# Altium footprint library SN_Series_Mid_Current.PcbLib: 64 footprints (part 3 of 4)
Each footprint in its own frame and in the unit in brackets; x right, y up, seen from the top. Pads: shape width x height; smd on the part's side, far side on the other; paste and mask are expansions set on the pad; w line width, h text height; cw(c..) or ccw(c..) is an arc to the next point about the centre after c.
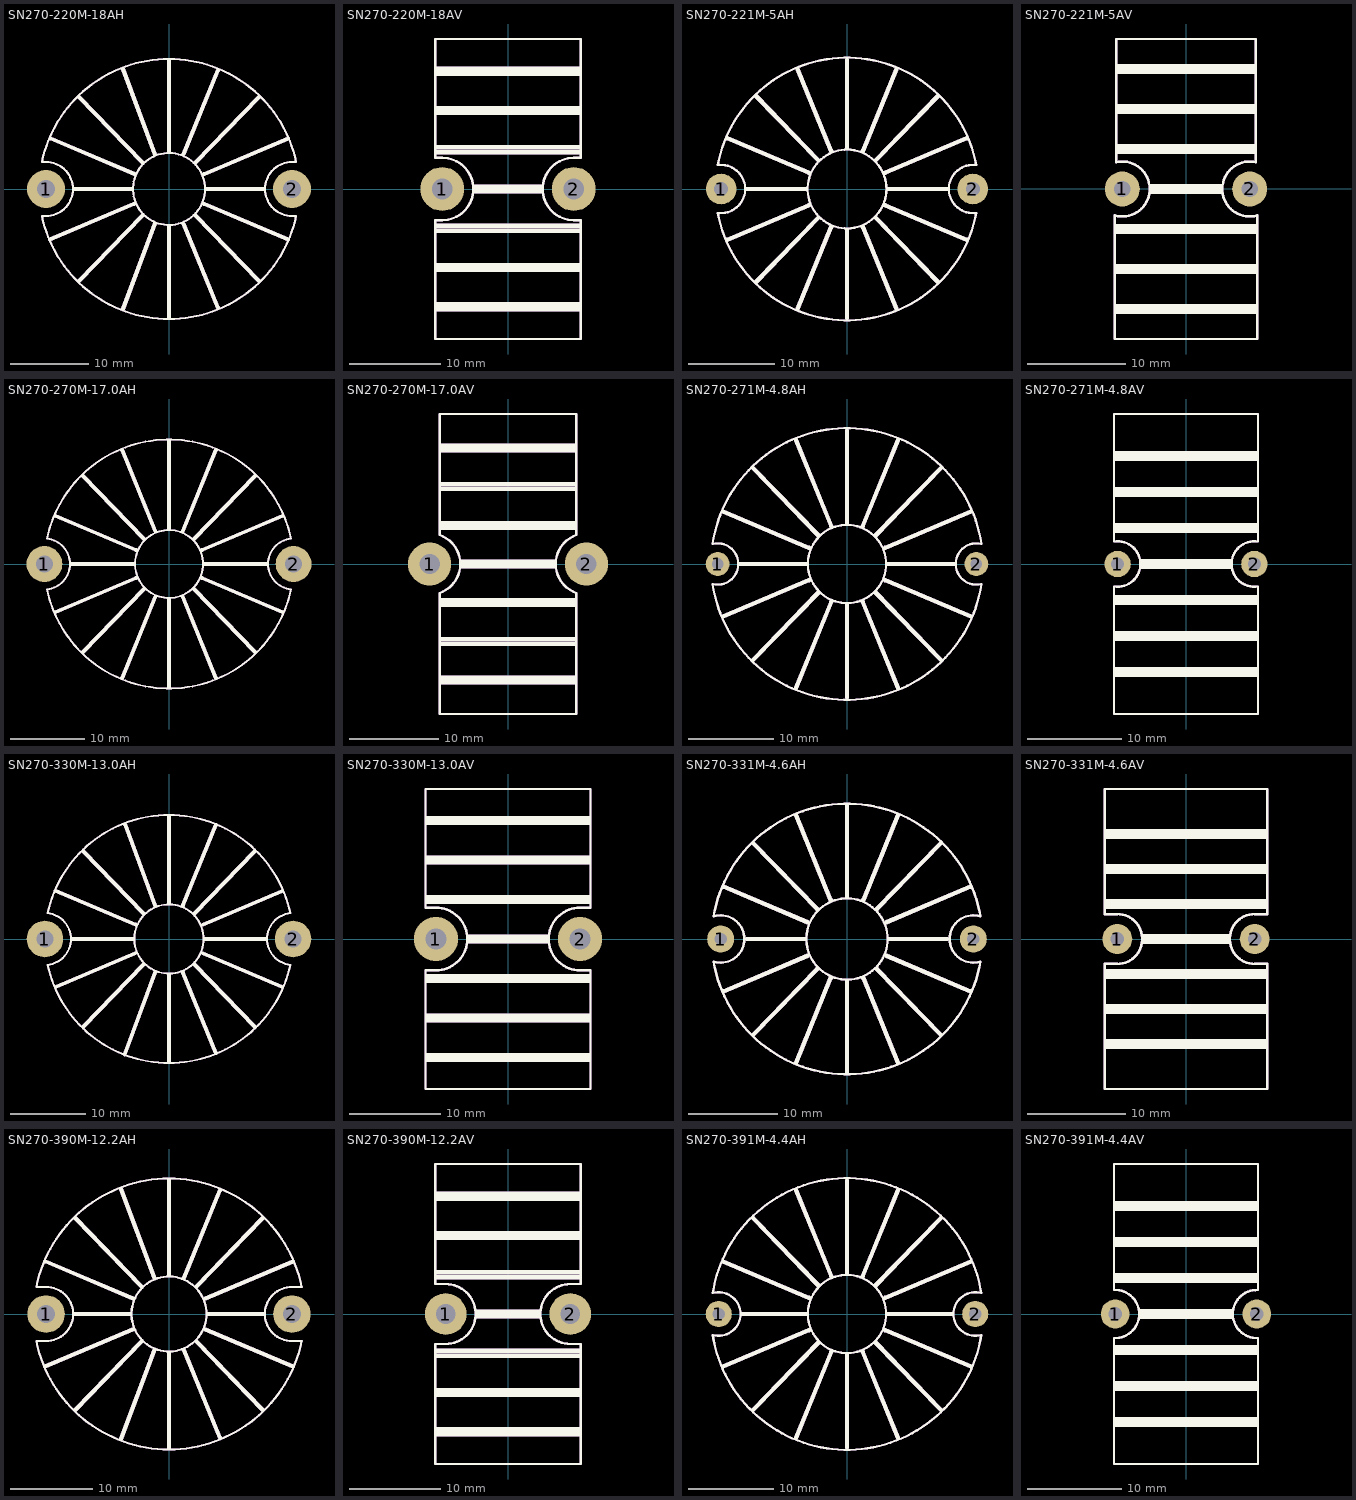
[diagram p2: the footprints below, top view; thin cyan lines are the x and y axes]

## SN270-220M-18AH [mil]
pads (2):
  round 190 hole 90: 1(-615,0) 2(615,0)
Top Overlay:
  circle w10: c0,0 r180
  lines w10: -635.83,-135 ccw(c0,0) 635.83,-135 615,-135 cw(c615,0) 615,135 635.83,135 ccw(c0,0) -635.83,135 -615,135 cw(c-615,0) -615,-135 -635.83,-135
  lines w19.68: -596.03,-252.56 -175.3,-74.28 ; -593.79,252.95 -173.05,74.68 ; -475,0 -185,0 ; -450,-460 -132.7,-132.43 ; -450,460 -132.7,132.43 ; -230,-600 -70.44,-171.87 ; -230,600 -70.44,171.87 ; 0,-640 0,-185 ; 0,185 0,640 ; 72.46,-173.99 243.97,-592.47 ; 72.46,173.99 243.97,592.47 ; 132.5,-132.5 450,-460 ; 132.5,132.5 450,460 ; 175.3,-74.28 596.03,-252.56 ; 175.3,74.28 596.03,252.56 ; 185,0 475,0
Mechanical 29:
  circle w10: c0,0 r180
  lines w10: -635.83,-135 ccw(c0,0) 635.83,-135 615,-135 cw(c615,0) 615,135 635.83,135 ccw(c0,0) -635.83,135 -615,135 cw(c-615,0) -615,-135 -635.83,-135
  lines w19.68: -596.03,-252.56 -175.3,-74.28 ; -593.79,252.95 -173.05,74.68 ; -475,0 -185,0 ; -450,-460 -132.7,-132.43 ; -450,460 -132.7,132.43 ; -230,-600 -70.44,-171.87 ; -230,600 -70.44,171.87 ; 0,-640 0,-185 ; 0,185 0,640 ; 72.46,-173.99 243.97,-592.47 ; 72.46,173.99 243.97,592.47 ; 132.5,-132.5 450,-460 ; 132.5,132.5 450,460 ; 175.3,-74.28 596.03,-252.56 ; 175.3,74.28 596.03,252.56 ; 185,0 475,0
  text "'.Designator'" at -290,145.15 h400

## SN270-220M-18AV [mil]
pads (2):
  round 190 hole 90: 1(-285,0) 2(285,0)
Top Overlay:
  lines w10: -315,-650 315,-650 315,-135 285,-135 cw(c285,0) 285,135 315,135 315,650 -315,650 -315,135 -285,135 cw(c-285,0) -285,-135 -315,-135 -315,-650
  lines w19.68: -310,-520 310,-520 ; -310,-500 310,-500 ; -310,-350 310,-350 ; -310,-330 310,-330 ; -310,-180 310,-180 ; -310,-160 310,-160 ; -310,160 310,160 ; -310,180 310,180 ; -310,330 310,330 ; -310,350 310,350 ; -310,500 310,500 ; -310,520 310,520 ; -145,-10 145,-10 ; -145,10 145,10
Mechanical 29:
  lines w10: -315,-650 315,-650 315,-135 285,-135 cw(c285,0) 285,135 315,135 315,650 -315,650 -315,135 -285,135 cw(c-285,0) -285,-135 -315,-135 -315,-650
  lines w19.68: -310,-520 310,-520 ; -310,-500 310,-500 ; -310,-350 310,-350 ; -310,-330 310,-330 ; -310,-180 310,-180 ; -310,-160 310,-160 ; -310,160 310,160 ; -310,180 310,180 ; -310,330 310,330 ; -310,350 310,350 ; -310,500 310,500 ; -310,520 310,520 ; -145,-10 145,-10 ; -145,10 145,10
  text "'.Designator'" at -1750,-64.85 h400

## SN270-221M-5AH [mil]
pads (2):
  round 140 hole 65: 1(-575,0) 2(575,0)
Top Overlay:
  circle w10: c0,0 r180
  lines w10: -589.93,-109.45 ccw(c0,0) 589.93,-109.45 ; -589.93,109.45 cw(c0,0) 589.93,109.45 ; -589.87,-108.99 ccw(c-575,0) -589.87,108.99 ; 589.87,-108.99 cw(c575,0) 589.87,108.99
  lines w19.68: -548.21,-232.29 -175.3,-74.28 ; -548.21,232.29 -175.3,74.28 ; -460,0 -185,0 ; -414.4,-423.28 -132.5,-132.5 ; -414.4,423.28 -132.5,132.5 ; -226.04,-548.74 -72.46,-173.99 ; -226.04,548.74 -72.46,173.99 ; 0,-590 0,-185 ; 0,185 0,590 ; 72.46,-173.99 226.04,-548.74 ; 72.46,173.99 226.04,548.74 ; 132.5,-132.5 414.4,-423.28 ; 132.5,132.5 414.4,423.28 ; 175.3,-74.28 548.21,-232.29 ; 175.3,74.28 548.21,232.29 ; 185,0 460,0
Mechanical 29:
  circle w10: c0,0 r180
  lines w10: -589.93,-109.45 ccw(c0,0) 589.93,-109.45 ; -589.93,109.45 cw(c0,0) 589.93,109.45 ; -589.87,-108.99 ccw(c-575,0) -589.87,108.99 ; 589.87,-108.99 cw(c575,0) 589.87,108.99
  lines w19.68: -548.21,-232.29 -175.3,-74.28 ; -548.21,232.29 -175.3,74.28 ; -460,0 -185,0 ; -414.4,-423.28 -132.5,-132.5 ; -414.4,423.28 -132.5,132.5 ; -226.04,-548.74 -72.46,-173.99 ; -226.04,548.74 -72.46,173.99 ; 0,-590 0,-185 ; 0,185 0,590 ; 72.46,-173.99 226.04,-548.74 ; 72.46,173.99 226.04,548.74 ; 132.5,-132.5 414.4,-423.28 ; 132.5,132.5 414.4,423.28 ; 175.3,-74.28 548.21,-232.29 ; 175.3,74.28 548.21,232.29 ; 185,0 460,0
  text "'.Designator'" at -290,145.15 h400

## SN270-221M-5AV [mil]
pads (2):
  round 140 hole 65: 1(-255,0) 2(255,0)
Top Overlay:
  lines w10: -285,-106.19 -285,-600 285,-600 285,-106.19 ; -284.91,-105.86 ccw(c-255,0) -279.95,107.13 ; -280,107.37 -280,600 280,600 280,107.37 ; 279.95,107.13 ccw(c255,0) 284.91,-105.86
  lines w19.68: -280,-170 280,-170 ; -280,-150 280,-150 ; -277,-490 278,-490 ; -277,-470 278,-470 ; -277,-330 278,-330 ; -277,-310 278,-310 ; -275,150 271,150 ; -275,170 271,170 ; -275,310 271,310 ; -275,330 271,330 ; -275,470 271,470 ; -275,490 271,490 ; -140,-10 140,-10 ; -140,10 140,10
Mechanical 29:
  lines w10: -285,-106.19 -285,-600 285,-600 285,-106.19 ; -284.91,-105.86 ccw(c-255,0) -279.95,107.13 ; -280,107.37 -280,600 280,600 280,107.37 ; 279.95,107.13 ccw(c255,0) 284.91,-105.86
  lines w19.68: -280,-170 280,-170 ; -280,-150 280,-150 ; -277,-490 278,-490 ; -277,-470 278,-470 ; -277,-330 278,-330 ; -277,-310 278,-310 ; -275,150 271,150 ; -275,170 271,170 ; -275,310 271,310 ; -275,330 271,330 ; -275,470 271,470 ; -275,490 271,490 ; -140,-10 140,-10 ; -140,10 140,10
  text "'.Designator'" at -1750,-64.85 h400

## SN270-270M-17.0AH [mil]
pads (2):
  round 190 hole 90: 1(-660,0) 2(660,0)
Top Overlay:
  circle w10: c0,0 r180
  lines w10: -646.19,-134.29 ccw(c0,0) 646.19,-134.29 cw(c660,0) 646.19,134.29 ccw(c0,0) -646.19,134.29 cw(c-660,0) -646.19,-134.29
  lines w19.68: -603.45,-255.7 -175.3,-74.28 ; -603.45,255.7 -175.3,74.28 ; -520,0 -185,0 ; -456.17,-466.36 -132.5,-132.5 ; -456.17,466.36 -132.5,132.5 ; -248.8,-604.26 -72.46,-173.99 ; -248.8,604.26 -72.46,173.99 ; 0,-650 0,-185 ; 0,185 0,650 ; 72.46,-173.99 248.8,-604.26 ; 72.46,173.99 248.8,604.26 ; 132.5,-132.5 456.17,-466.36 ; 132.5,132.5 456.17,466.36 ; 175.3,-74.28 603.45,-255.7 ; 175.3,74.28 603.45,255.7 ; 185,0 520,0
Mechanical 29:
  circle w10: c0,0 r180
  lines w10: -646.19,-134.29 ccw(c0,0) 646.19,-134.29 cw(c660,0) 646.19,134.29 ccw(c0,0) -646.19,134.29 cw(c-660,0) -646.19,-134.29
  lines w19.68: -603.45,-255.7 -175.3,-74.28 ; -603.45,255.7 -175.3,74.28 ; -520,0 -185,0 ; -456.17,-466.36 -132.5,-132.5 ; -456.17,466.36 -132.5,132.5 ; -248.8,-604.26 -72.46,-173.99 ; -248.8,604.26 -72.46,173.99 ; 0,-650 0,-185 ; 0,185 0,650 ; 72.46,-173.99 248.8,-604.26 ; 72.46,173.99 248.8,604.26 ; 132.5,-132.5 456.17,-466.36 ; 132.5,132.5 456.17,466.36 ; 175.3,-74.28 603.45,-255.7 ; 175.3,74.28 603.45,255.7 ; 185,0 520,0
  text "'.Designator'" at -290,145.15 h400

## SN270-270M-17.0AV [mil]
pads (2):
  round 190 hole 90: 1(-345,0) 2(345,0)
Top Overlay:
  lines w10: -300.09,127.31 cw(c-345,0) -300,-127.28 -300,-660 300,-660 300,-127.57 ; -300,127.57 -300,660 300,660 300,127.57 ; 300.09,-127.31 cw(c345,0) 300.09,127.31
  lines w19.68: -295,-520 295,-520 ; -295,-500 295,-500 ; -295,-350 295,-350 ; -295,-330 295,-330 ; -295,-180 295,-180 ; -295,-160 295,-160 ; -295,160 295,160 ; -295,180 295,180 ; -295,330 295,330 ; -295,350 295,350 ; -295,500 295,500 ; -295,520 295,520 ; -205,-10 205,-10 ; -205,10 205,10
Mechanical 29:
  lines w10: -300.09,127.31 cw(c-345,0) -300,-127.28 -300,-660 300,-660 300,-127.57 ; -300,127.57 -300,660 300,660 300,127.57 ; 300.09,-127.31 cw(c345,0) 300.09,127.31
  lines w19.68: -295,-520 295,-520 ; -295,-500 295,-500 ; -295,-350 295,-350 ; -295,-330 295,-330 ; -295,-180 295,-180 ; -295,-160 295,-160 ; -295,160 295,160 ; -295,180 295,180 ; -295,330 295,330 ; -295,350 295,350 ; -295,500 295,500 ; -295,520 295,520 ; -205,-10 205,-10 ; -205,10 205,10
  text "'.Designator'" at -1750,-64.85 h400

## SN270-271M-4.8AH [mil]
pads (2):
  round 110 hole 53: 1(-595,0) 2(595,0)
Top Overlay:
  circle w10: c0,0 r180
  lines w10: -618.06,-92.87 ccw(c0,0) 618.05,-92.95 ; -618.06,92.87 cw(c0,0) 618.08,92.76 ; -617.89,-92.2 ccw(c-595,0) -617.89,92.2 ; 617.87,-92.21 cw(c595,0) 617.94,92.19
  lines w19.68: -569.45,-241.29 -175.3,-74.28 ; -569.45,241.29 -175.3,74.28 ; -495,0 -185,0 ; -430.31,-439.69 -132.5,-132.5 ; -430.31,439.69 -132.5,132.5 ; -234.79,-570.09 -72.46,-173.99 ; -234.79,570.09 -72.46,173.99 ; 0,-615 0,-185 ; 0,185 0,615 ; 72.46,-173.99 234.79,-570.09 ; 72.46,173.99 234.79,570.09 ; 132.5,-132.5 430.31,-439.69 ; 132.5,132.5 430.31,439.69 ; 175.3,-74.28 569.45,-241.29 ; 175.3,74.28 569.45,241.29 ; 185,0 495,0
Mechanical 29:
  circle w10: c0,0 r180
  lines w10: -618.06,-92.87 ccw(c0,0) 618.05,-92.95 ; -618.06,92.87 cw(c0,0) 618.08,92.76 ; -617.89,-92.2 ccw(c-595,0) -617.89,92.2 ; 617.87,-92.21 cw(c595,0) 617.94,92.19
  lines w19.68: -569.45,-241.29 -175.3,-74.28 ; -569.45,241.29 -175.3,74.28 ; -495,0 -185,0 ; -430.31,-439.69 -132.5,-132.5 ; -430.31,439.69 -132.5,132.5 ; -234.79,-570.09 -72.46,-173.99 ; -234.79,570.09 -72.46,173.99 ; 0,-615 0,-185 ; 0,185 0,615 ; 72.46,-173.99 234.79,-570.09 ; 72.46,173.99 234.79,570.09 ; 132.5,-132.5 430.31,-439.69 ; 132.5,132.5 430.31,439.69 ; 175.3,-74.28 569.45,-241.29 ; 175.3,74.28 569.45,241.29 ; 185,0 495,0
  text "'.Designator'" at -290,145.15 h400

## SN270-271M-4.8AV [mil]
pads (2):
  round 110 hole 53: 1(-285,0) 2(285,0)
Top Overlay:
  lines w10: -300,-94.05 -300,-625 300,-625 300,-93.95 ; -300,94.05 -300,625 300,625 300,94.05 ; -299.96,-93.81 ccw(c-285,0) -299.96,93.81 ; 299.09,-93.95 cw(c285,0) 299.96,93.81
  lines w19.68: -295,-460 295,-460 ; -295,-440 295,-440 ; -295,-310 295,-310 ; -295,-290 295,-290 ; -295,-160 295,-160 ; -295,-140 295,-140 ; -295,140 295,140 ; -295,160 295,160 ; -295,290 295,290 ; -295,310 295,310 ; -295,440 295,440 ; -295,460 295,460 ; -185,-10 185,-10 ; -185,10 185,10
Mechanical 29:
  lines w10: -300,-94.05 -300,-625 300,-625 300,-93.95 ; -300,94.05 -300,625 300,625 300,94.05 ; -299.96,-93.81 ccw(c-285,0) -299.96,93.81 ; 299.09,-93.95 cw(c285,0) 299.96,93.81
  lines w19.68: -295,-460 295,-460 ; -295,-440 295,-440 ; -295,-310 295,-310 ; -295,-290 295,-290 ; -295,-160 295,-160 ; -295,-140 295,-140 ; -295,140 295,140 ; -295,160 295,160 ; -295,290 295,290 ; -295,310 295,310 ; -295,440 295,440 ; -295,460 295,460 ; -185,-10 185,-10 ; -185,10 185,10
  text "'.Designator'" at -1750,-64.85 h400

## SN270-330M-13.0AH [mil]
pads (2):
  round 190 hole 90: 1(-645,0) 2(645,0)
Top Overlay:
  circle w10: c0,0 r180
  lines w10: -630.87,-134.26 ccw(c-645,0) -630.87,134.26 cw(c0,0) 630.87,134.26 ccw(c645,0) 630.87,-134.26 cw(c0,0) -630.87,-134.26
  lines w19.68: -589.51,251.14 -173.05,74.68 ; -585.76,-248.2 -175.3,-74.28 ; -505,0 -185,0 ; -445.08,-454.92 -132.7,-132.43 ; -445.08,454.92 -132.7,132.43 ; -230,-600 -70.44,-171.87 ; -228.36,595.61 -70.44,171.87 ; 0,-640 0,-185 ; 0,185 0,640 ; 72.46,-173.99 243.97,-592.47 ; 72.46,173.99 243.97,592.47 ; 132.5,-132.5 447.58,-457.5 ; 132.5,132.5 445.08,454.92 ; 175.3,-74.28 585.76,-248.2 ; 175.3,74.28 585.76,248.2 ; 185,0 505,0
Mechanical 29:
  circle w10: c0,0 r180
  lines w10: -630.87,-134.26 ccw(c-645,0) -630.87,134.26 cw(c0,0) 630.87,134.26 ccw(c645,0) 630.87,-134.26 cw(c0,0) -630.87,-134.26
  lines w19.68: -589.51,251.14 -173.05,74.68 ; -585.76,-248.2 -175.3,-74.28 ; -505,0 -185,0 ; -445.08,-454.92 -132.7,-132.43 ; -445.08,454.92 -132.7,132.43 ; -230,-600 -70.44,-171.87 ; -228.36,595.61 -70.44,171.87 ; 0,-640 0,-185 ; 0,185 0,640 ; 72.46,-173.99 243.97,-592.47 ; 72.46,173.99 243.97,592.47 ; 132.5,-132.5 447.58,-457.5 ; 132.5,132.5 445.08,454.92 ; 175.3,-74.28 585.76,-248.2 ; 175.3,74.28 585.76,248.2 ; 185,0 505,0
  text "'.Designator'" at -290,145.15 h400

## SN270-330M-13.0AV [mil]
pads (2):
  round 190 hole 90: 1(-310,0) 2(310,0)
Top Overlay:
  lines w10: -355,-645 355,-645 355,-135 310,-135 cw(c310,0) 310,135 355,135 355,645 -355,645 -355,135 -310,135 cw(c-310,0) -310,-135 -355,-135 -355,-645
  lines w19.68: -350,-520 350,-520 ; -350,-500 350,-500 ; -350,-350 350,-350 ; -350,-330 350,-330 ; -350,-180 350,-180 ; -350,-160 350,-160 ; -350,160 350,160 ; -350,180 350,180 ; -350,330 350,330 ; -350,350 350,350 ; -350,500 350,500 ; -350,520 350,520 ; -170,-10 170,-10 ; -170,10 170,10
Mechanical 29:
  lines w10: -355,-645 355,-645 355,-135 310,-135 cw(c310,0) 310,135 355,135 355,645 -355,645 -355,135 -310,135 cw(c-310,0) -310,-135 -355,-135 -355,-645
  lines w19.68: -350,-520 350,-520 ; -350,-500 350,-500 ; -350,-350 350,-350 ; -350,-330 350,-330 ; -350,-180 350,-180 ; -350,-160 350,-160 ; -350,160 350,160 ; -350,180 350,180 ; -350,330 350,330 ; -350,350 350,350 ; -350,500 350,500 ; -350,520 350,520 ; -170,-10 170,-10 ; -170,10 170,10
  text "'.Designator'" at -1750,-64.85 h400

## SN270-331M-4.6AH [mil]
pads (2):
  round 120 hole 55: 1(-560,0) 2(560,0)
Top Overlay:
  circle w10: c0,0 r180
  lines w10: -591.4,-101.22 ccw(c0,0) 591.4,-101.22 ; -591.4,101.22 cw(c0,0) 591.37,101.39 ; -591.11,-100.29 ccw(c-560,0) -591.11,100.29 ; 591.04,100.31 ccw(c560,0) 591.11,-100.29
  lines w19.68: -548.21,-232.29 -175.3,-74.28 ; -548.21,232.29 -175.3,74.28 ; -445,0 -185,0 ; -414.4,-423.28 -132.5,-132.5 ; -414.4,423.28 -132.5,132.5 ; -226.04,-548.74 -72.46,-173.99 ; -226.04,548.74 -72.46,173.99 ; 0,-590 0,-185 ; 0,185 0,590 ; 72.46,-173.99 226.04,-548.74 ; 72.46,173.99 226.04,548.74 ; 132.5,-132.5 414.4,-423.28 ; 132.5,132.5 414.4,423.28 ; 175.3,-74.28 548.21,-232.29 ; 175.3,74.28 548.21,232.29 ; 185,0 445,0
Mechanical 29:
  circle w10: c0,0 r180
  lines w10: -591.4,-101.22 ccw(c0,0) 591.4,-101.22 ; -591.4,101.22 cw(c0,0) 591.37,101.39 ; -591.11,-100.29 ccw(c-560,0) -591.11,100.29 ; 591.04,100.31 ccw(c560,0) 591.11,-100.29
  lines w19.68: -548.21,-232.29 -175.3,-74.28 ; -548.21,232.29 -175.3,74.28 ; -445,0 -185,0 ; -414.4,-423.28 -132.5,-132.5 ; -414.4,423.28 -132.5,132.5 ; -226.04,-548.74 -72.46,-173.99 ; -226.04,548.74 -72.46,173.99 ; 0,-590 0,-185 ; 0,185 0,590 ; 72.46,-173.99 226.04,-548.74 ; 72.46,173.99 226.04,548.74 ; 132.5,-132.5 414.4,-423.28 ; 132.5,132.5 414.4,423.28 ; 175.3,-74.28 548.21,-232.29 ; 175.3,74.28 548.21,232.29 ; 185,0 445,0
  text "'.Designator'" at -290,145.15 h400

## SN270-331M-4.6AV [mil]
pads (2):
  round 120 hole 55: 1(-275,0) 2(275,0)
Top Overlay:
  lines w10: -325,-600 -325,-100 -275,-100 ccw(c-275,0) -275,100 -325,100 -325,600 325,600 325,100 275,100 ccw(c275,0) 275,-100 325,-100 325,-600 -325,-600
  lines w19.68: -320,-430 320,-430 ; -320,-410 320,-410 ; -320,-290 320,-290 ; -320,-270 320,-270 ; -320,-150 320,-150 ; -320,-130 320,-130 ; -320,130 320,130 ; -320,150 320,150 ; -320,270 320,270 ; -320,290 320,290 ; -320,410 320,410 ; -320,430 320,430 ; -170,-10 170,-10 ; -170,10 170,10
Mechanical 29:
  lines w10: -325,-600 -325,-100 -275,-100 ccw(c-275,0) -275,100 -325,100 -325,600 325,600 325,100 275,100 ccw(c275,0) 275,-100 325,-100 325,-600 -325,-600
  lines w19.68: -320,-430 320,-430 ; -320,-410 320,-410 ; -320,-290 320,-290 ; -320,-270 320,-270 ; -320,-150 320,-150 ; -320,-130 320,-130 ; -320,130 320,130 ; -320,150 320,150 ; -320,270 320,270 ; -320,290 320,290 ; -320,410 320,410 ; -320,430 320,430 ; -170,-10 170,-10 ; -170,10 170,10
  text "'.Designator'" at -1750,-64.85 h400

## SN270-390M-12.2AH [mil]
pads (2):
  round 180 hole 85: 1(-590,0) 2(590,0)
Top Overlay:
  circle w10: c0,0 r180
  lines w10: -637,-130 -590,-130 ccw(c-590,0) -590,130 -637,130 ; -636.87,-130 ccw(c0,0) 636.87,-130 ; -636.87,130 cw(c0,0) 636.87,130 ; 637,-130 590,-130 cw(c590,0) 590,130 637,130
  lines w19.68: -596.03,-252.56 -175.3,-74.28 ; -593.79,252.95 -173.05,74.68 ; -455,0 -185,0 ; -450,-460 -132.7,-132.43 ; -450,460 -132.7,132.43 ; -230,-600 -70.44,-171.87 ; -230,600 -70.44,171.87 ; 0,-640 0,-185 ; 0,185 0,640 ; 72.46,-173.99 243.97,-592.47 ; 72.46,173.99 243.97,592.47 ; 132.5,-132.5 450,-460 ; 132.5,132.5 450,460 ; 175.3,-74.28 596.03,-252.56 ; 175.3,74.28 596.03,252.56 ; 185,0 455,0
Mechanical 29:
  circle w10: c0,0 r180
  lines w10: -637,-130 -590,-130 ccw(c-590,0) -590,130 -637,130 ; -636.87,-130 ccw(c0,0) 636.87,-130 ; -636.87,130 cw(c0,0) 636.87,130 ; 637,-130 590,-130 cw(c590,0) 590,130 637,130
  lines w19.68: -596.03,-252.56 -175.3,-74.28 ; -593.79,252.95 -173.05,74.68 ; -455,0 -185,0 ; -450,-460 -132.7,-132.43 ; -450,460 -132.7,132.43 ; -230,-600 -70.44,-171.87 ; -230,600 -70.44,171.87 ; 0,-640 0,-185 ; 0,185 0,640 ; 72.46,-173.99 243.97,-592.47 ; 72.46,173.99 243.97,592.47 ; 132.5,-132.5 450,-460 ; 132.5,132.5 450,460 ; 175.3,-74.28 596.03,-252.56 ; 175.3,74.28 596.03,252.56 ; 185,0 455,0
  text "'.Designator'" at -290,145.15 h400

## SN270-390M-12.2AV [mil]
pads (2):
  round 180 hole 85: 1(-270,0) 2(270,0)
Top Overlay:
  lines w10: -315,-650 315,-650 315,-130 270,-130 cw(c270,0) 270,130 315,130 315,650 -315,650 -315,130 -270,130 cw(c-270,0) -270,-130 -315,-130 -315,-650
  lines w19.68: -310,-520 310,-520 ; -310,-500 310,-500 ; -310,-350 310,-350 ; -310,-330 310,-330 ; -310,-180 310,-180 ; -310,-160 310,-160 ; -310,160 310,160 ; -310,180 310,180 ; -310,330 310,330 ; -310,350 310,350 ; -310,500 310,500 ; -310,520 310,520 ; -135,-10 135,-10 ; -135,10 135,10
Mechanical 29:
  lines w10: -315,-650 315,-650 315,-130 270,-130 cw(c270,0) 270,130 315,130 315,650 -315,650 -315,130 -270,130 cw(c-270,0) -270,-130 -315,-130 -315,-650
  lines w19.68: -310,-520 310,-520 ; -310,-500 310,-500 ; -310,-350 310,-350 ; -310,-330 310,-330 ; -310,-180 310,-180 ; -310,-160 310,-160 ; -310,160 310,160 ; -310,180 310,180 ; -310,330 310,330 ; -310,350 310,350 ; -310,500 310,500 ; -310,520 310,520 ; -135,-10 135,-10 ; -135,10 135,10
  text "'.Designator'" at -1750,-64.85 h400

## SN270-391M-4.4AH [mil]
pads (2):
  round 120 hole 57: 1(-590,0) 2(590,0)
Top Overlay:
  circle w10: c0,0 r180
  lines w10: -617.53,-96.34 ccw(c0,0) 617.53,-96.34 ; -617.37,97.38 cw(c0,0) 617.37,97.38 ; -617.07,-96.27 ccw(c-590,0) -617.06,96.27 ; 617.06,-96.27 cw(c590,0) 617.06,96.27
  lines w19.68: -569.45,-241.29 -175.3,-74.28 ; -569.45,241.29 -175.3,74.28 ; -485,0 -185,0 ; -430.31,-439.69 -132.5,-132.5 ; -430.31,439.69 -132.5,132.5 ; -234.79,-570.09 -72.46,-173.99 ; -234.79,570.09 -72.46,173.99 ; 0,-615 0,-185 ; 0,185 0,615 ; 72.46,-173.99 234.79,-570.09 ; 72.46,173.99 234.79,570.09 ; 132.5,-132.5 430.31,-439.69 ; 132.5,132.5 430.31,439.69 ; 175.3,-74.28 569.45,-241.29 ; 175.3,74.28 569.45,241.29 ; 185,0 485,0
Mechanical 29:
  circle w10: c0,0 r180
  lines w10: -617.53,-96.34 ccw(c0,0) 617.53,-96.34 ; -617.37,97.38 cw(c0,0) 617.37,97.38 ; -617.07,-96.27 ccw(c-590,0) -617.06,96.27 ; 617.06,-96.27 cw(c590,0) 617.06,96.27
  lines w19.68: -569.45,-241.29 -175.3,-74.28 ; -569.45,241.29 -175.3,74.28 ; -485,0 -185,0 ; -430.31,-439.69 -132.5,-132.5 ; -430.31,439.69 -132.5,132.5 ; -234.79,-570.09 -72.46,-173.99 ; -234.79,570.09 -72.46,173.99 ; 0,-615 0,-185 ; 0,185 0,615 ; 72.46,-173.99 234.79,-570.09 ; 72.46,173.99 234.79,570.09 ; 132.5,-132.5 430.31,-439.69 ; 132.5,132.5 430.31,439.69 ; 175.3,-74.28 569.45,-241.29 ; 175.3,74.28 569.45,241.29 ; 185,0 485,0
  text "'.Designator'" at -290,145.15 h400

## SN270-391M-4.4AV [mil]
pads (2):
  round 120 hole 57: 1(-295,0) 2(295,0)
Top Overlay:
  lines w10: 299.27,99.91 ccw(c295,0) 299.99,-99.88 300,-625 -300,-625 -300,-99.88 ccw(c-295,0) -299.99,99.88 -300,625 300,625 300,99.91
  lines w19.68: -295,-460 295,-460 ; -295,-440 295,-440 ; -295,-310 295,-310 ; -295,-290 295,-290 ; -295,-160 295,-160 ; -295,-140 295,-140 ; -295,140 295,140 ; -295,160 295,160 ; -295,290 295,290 ; -295,310 295,310 ; -295,440 295,440 ; -295,460 295,460 ; -190,-10 190,-10 ; -190,10 190,10
Mechanical 29:
  lines w10: 299.27,99.91 ccw(c295,0) 299.99,-99.88 300,-625 -300,-625 -300,-99.88 ccw(c-295,0) -299.99,99.88 -300,625 300,625 300,99.91
  lines w19.68: -295,-460 295,-460 ; -295,-440 295,-440 ; -295,-310 295,-310 ; -295,-290 295,-290 ; -295,-160 295,-160 ; -295,-140 295,-140 ; -295,140 295,140 ; -295,160 295,160 ; -295,290 295,290 ; -295,310 295,310 ; -295,440 295,440 ; -295,460 295,460 ; -190,-10 190,-10 ; -190,10 190,10
  text "'.Designator'" at -1750,-64.85 h400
